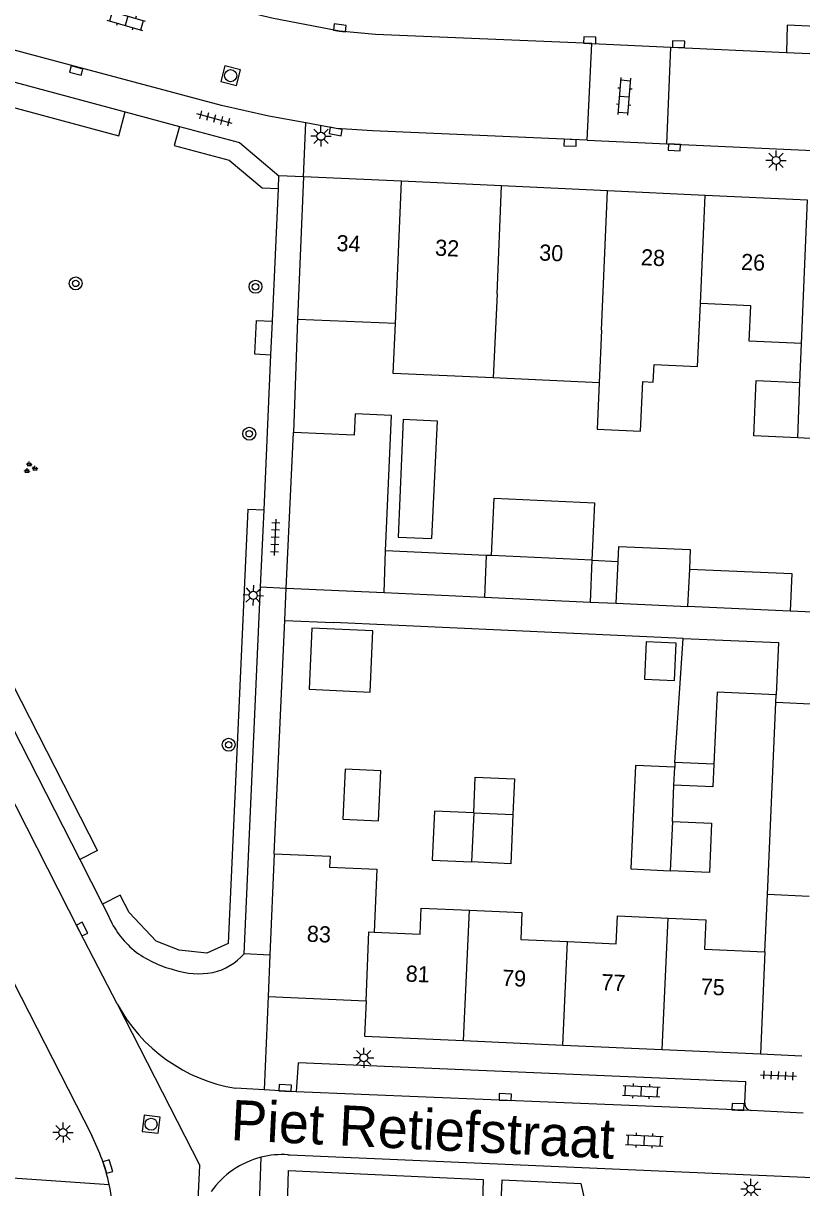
# Model space of a CAD drawing. Extents: x 132994 to 136000, y 393499 to 395512.
# Drawn here: x 133154 to 133202.2, y 395339 to 395411.1 of the extents above; entities that cross this region are included whole.
import ezdxf

# ---------------------------------------------------------------- set-up
doc = ezdxf.new("R2010")
doc.units = 0
for name, color, linetype in [('gg-afsc-erfafscheiding', 7, 'Continuous'), ('gg-afsc-hekwerk', 7, 'Continuous'), ('gg-afsc-muur', 7, 'Continuous'), ('gg-anno-huisnummerreeks BGT', 7, 'Continuous'), ('gg-anno-openbare ruimte label', 7, 'Continuous'), ('gg-bbg-bijgebouw', 7, 'Continuous'), ('gg-bbg-gedigitaliseerde bebouwing', 7, 'Continuous'), ('gg-bbg-gedigitaliseerde bijgebouw', 7, 'Continuous'), ('gg-bbg-hoofdgebouw', 7, 'Continuous'), ('gg-bbg-luifel en loopbrug', 7, 'Continuous'), ('gg-bbg-tussenscheiding', 7, 'Continuous'), ('gg-knt-verharding', 7, 'Continuous'), ('gg-knt-verharding nz', 7, 'Continuous'), ('gt-grn-groengrens', 7, 'Continuous'), ('gt-grn-weggrens', 7, 'Continuous'), ('gt-symb-boom', 7, 'Continuous'), ('gt-symb-groenvak', 7, 'Continuous'), ('gt-symb-klinker verharding', 7, 'Continuous'), ('gt-symb-kolk', 7, 'Continuous'), ('gt-symb-lichtmast', 7, 'Continuous'), ('gt-symb-rioolschacht', 7, 'Continuous'), ('gt-symb-tegel verharding', 7, 'Continuous')]:
    doc.layers.add(name, color=color, linetype=linetype)

# ---------------------------------------------------------------- blocks, each defined once
blk = doc.blocks.new('gt0-KOLK')
at = {"layer": 'gt-symb-kolk'}
blk.add_lwpolyline([(0, 0), (0.375, 0), (0.375, 0.4), (-0.375, 0.4), (-0.375, 0), (0, 0)], dxfattribs=at)
blk = doc.blocks.new('gt0-KL1')
at = {"layer": 'gt-symb-klinker verharding'}
for p, q in [((-1.15, 0.3), (1.15, 0.3)), ((-1, -0.3), (-1, 0.3)), ((-0.5, 0.3), (-0.5, 0.45)), ((0, -0.3), (0, 0.3)), ((0.5, 0.3), (0.5, 0.45)), ((1, -0.3), (1, 0.3)), ((-1.15, -0.3), (1.15, -0.3)), ((-0.5, -0.45), (-0.5, -0.3)), ((0.5, -0.45), (0.5, -0.3))]:
    blk.add_line(p, q, dxfattribs=at)
blk = doc.blocks.new('gt0-LMAST')
at = {"layer": 'gt-symb-lichtmast'}
for p, q in [((-0.182, 0.173), (-0.447, 0.438)), ((-0.005, 0.246), (-0.005, 0.621)), ((0.172, 0.173), (0.437, 0.438)), ((-0.255, -0.004), (-0.63, -0.004)), ((-0.182, -0.181), (-0.447, -0.446)), ((-0.005, -0.254), (-0.005, -0.629)), ((0.437, -0.446), (0.172, -0.181)), ((0.245, -0.004), (0.62, -0.004))]:
    blk.add_line(p, q, dxfattribs=at)
blk.add_circle((-0.005, -0.004), 0.25, dxfattribs=at)
blk = doc.blocks.new('gt0-TEG1')
at = {"layer": 'gt-symb-tegel verharding'}
for p, q in [((-1.125, 0), (1.125, 0)), ((-0.9, -0.25), (-0.9, 0.25)), ((-0.45, -0.25), (-0.45, 0.25)), ((0, -0.25), (0, 0.25)), ((0.45, -0.25), (0.45, 0.25)), ((0.9, -0.25), (0.9, 0.25))]:
    blk.add_line(p, q, dxfattribs=at)
blk = doc.blocks.new('gt0-BOOM')
at = {"layer": 'gt-symb-boom'}
for radius in [0.4, 0.2]:
    blk.add_circle((0, 0), radius, dxfattribs=at)
blk = doc.blocks.new('gt0-RS')
at = {"layer": 'gt-symb-rioolschacht'}
blk.add_lwpolyline([(-0.5, -0.5), (0.5, -0.5), (0.5, 0.5), (-0.5, 0.5)], close=True, dxfattribs=at)
blk.add_circle((0, 0), 0.375, dxfattribs=at)
blk = doc.blocks.new('gt0-GRVAK')
at = {"layer": 'gt-symb-groenvak'}
for p, q in [((-0.11, 0.189), (-0.228, 0.24)), ((-0.182, 0.153), (0.088, 0.153)), ((-0.091, 0.211), (-0.156, 0.322)), ((-0.047, 0.214), (-0.047, 0.393)), ((-0.004, 0.211), (0.061, 0.322)), ((0.015, 0.189), (0.133, 0.24)), ((0.262, -0.052), (0.197, 0.059)), ((0.305, -0.049), (0.305, 0.13)), ((0.349, -0.052), (0.414, 0.059)), ((-0.245, -0.228), (-0.363, -0.177)), ((-0.318, -0.264), (-0.047, -0.264)), ((-0.226, -0.206), (-0.291, -0.095)), ((-0.183, -0.203), (-0.183, -0.024)), ((-0.139, -0.206), (-0.074, -0.095)), ((-0.12, -0.228), (-0.002, -0.177)), ((0.243, -0.074), (0.125, -0.023)), ((0.17, -0.11), (0.441, -0.11)), ((0.368, -0.074), (0.486, -0.023))]:
    blk.add_line(p, q, dxfattribs=at)

msp = doc.modelspace()

# ---------------------------------------------------------------- linework, layer by layer
at = {"layer": 'gg-afsc-erfafscheiding'}
for p, q in [((133232.713, 395373.343), (133201.504, 395374.716)), ((133194.88, 395373.028), (133173.207, 395374.007)), ((133200.627, 395369.052), (133200.648, 395369.533)), ((133199.948, 395353.623), (133200.104, 395357.169))]:
    msp.add_line(p, q, dxfattribs=at)
at = {"layer": 'gg-afsc-hekwerk'}
for p, q in [((133170.21, 395374.142), (133170.3, 395376.14)), ((133199.67, 395347.31), (133202.23, 395347.18))]:
    msp.add_line(p, q, dxfattribs=at)
at = {"layer": 'gg-afsc-muur'}
for p, q in [((133170.99, 395392.77), (133170.74, 395385.78)), ((133169.555, 395359.692), (133170.21, 395374.142)), ((133170.21, 395374.142), (133173.207, 395374.007))]:
    msp.add_line(p, q, dxfattribs=at)
at = {"layer": 'gg-bbg-bijgebouw'}
msp.add_line((133170.3, 395376.14), (133170.74, 395385.78), dxfattribs=at)
msp.add_lwpolyline([(133173.809, 395361.838), (133176.009, 395361.722), (133176.161, 395364.82), (133173.955, 395364.928), (133173.809, 395361.838)], dxfattribs=at)
at = {"layer": 'gg-bbg-gedigitaliseerde bebouwing'}
for p, q in [((133177.065, 395392.515), (133170.99, 395392.77)), ((133202.11, 395388.875), (133202.222, 395391.286)), ((133189.68, 395388.845), (133183.119, 395389.149)), ((133175.908, 395358.733), (133175.748, 395354.841)), ((133199.948, 395353.623), (133199.67, 395347.31))]:
    msp.add_line(p, q, dxfattribs=at)
for points in [[(133189.68, 395388.845), (133189.547, 395385.989), (133192.246, 395385.864), (133192.387, 395388.927), (133193.031, 395388.897), (133193.082, 395389.993), (133195.779, 395389.868), (133195.96, 395393.768)], [(133202.222, 395391.286), (133198.972, 395391.436), (133199.073, 395393.624), (133195.96, 395393.768)], [(133183.119, 395389.149), (133176.922, 395389.436), (133177.065, 395392.515)], [(133205.425, 395391.093), (133205.315, 395388.726), (133204.925, 395388.745), (133204.766, 395385.305), (133201.976, 395385.434)], [(133175.748, 395354.841), (133178.591, 395354.716), (133178.662, 395356.331), (133181.645, 395356.2)], [(133181.645, 395356.2), (133184.895, 395356.057), (133184.821, 395354.382), (133187.723, 395354.254)], [(133187.723, 395354.254), (133190.738, 395354.121), (133190.814, 395355.838), (133193.951, 395355.699)], [(133193.951, 395355.699), (133196.29, 395355.596), (133196.21, 395353.788), (133199.948, 395353.623)]]:
    msp.add_lwpolyline(points, dxfattribs=at)
at = {"layer": 'gg-bbg-gedigitaliseerde bijgebouw'}
for p, q in [((133176.44, 395378.455), (133176.826, 395386.822)), ((133182.682, 395378.167), (133176.44, 395378.455)), ((133183.017, 395378.152), (133182.682, 395378.167)), ((133189.233, 395377.866), (133183.017, 395378.152)), ((133189.233, 395377.866), (133189.124, 395375.273)), ((133190.736, 395375.199), (133190.855, 395377.791)), ((133170.3, 395376.14), (133176.367, 395375.86)), ((133176.367, 395375.86), (133182.574, 395375.574)), ((133182.574, 395375.574), (133189.124, 395375.273)), ((133190.736, 395375.199), (133195.162, 395374.995)), ((133201.504, 395374.716), (133195.162, 395374.995)), ((133194.375, 395365.343), (133194.88, 395373.028)), ((133194.313, 395363.938), (133194.362, 395365.043)), ((133196.791, 395365.237), (133194.375, 395365.343)), ((133194.214, 395361.684), (133194.313, 395363.938)), ((133181.91, 395362.225), (133184.336, 395362.118))]:
    msp.add_line(p, q, dxfattribs=at)
for points in [[(133201.976, 395385.434), (133199.253, 395385.56), (133199.413, 395389.001), (133202.11, 395388.875)], [(133176.826, 395386.822), (133174.564, 395386.925), (133174.504, 395385.614), (133170.74, 395385.78)], [(133177.543, 395386.589), (133177.237, 395379.295), (133179.301, 395379.209)], [(133177.543, 395386.589), (133179.637, 395386.492), (133179.301, 395379.209)], [(133190.855, 395377.791), (133190.898, 395378.724), (133195.324, 395378.52), (133195.269, 395377.315)], [(133195.269, 395377.315), (133201.606, 395377.036), (133201.504, 395374.716)], [(133171.892, 395373.653), (133171.721, 395369.873), (133175.501, 395369.702), (133175.672, 395373.483), (133171.892, 395373.653)], [(133192.49, 395370.499), (133194.355, 395370.415), (133194.46, 395372.736), (133192.595, 395372.82), (133192.49, 395370.499)], [(133194.88, 395373.028), (133200.79, 395372.769), (133200.648, 395369.533)], [(133200.648, 395369.533), (133196.987, 395369.694), (133196.791, 395365.237)], [(133194.362, 395365.043), (133191.936, 395365.15), (133191.639, 395358.748), (133194.08, 395358.641)], [(133181.91, 395362.225), (133179.484, 395362.331), (133179.335, 395359.289), (133181.776, 395359.182)], [(133184.336, 395362.118), (133184.218, 395359.075), (133181.776, 395359.182)], [(133194.214, 395361.684), (133196.64, 395361.577), (133196.522, 395358.534), (133194.08, 395358.641)]]:
    msp.add_lwpolyline(points, dxfattribs=at)
at = {"layer": 'gg-bbg-hoofdgebouw'}
for p, q in [((133171.36, 395401.61), (133170.99, 395392.77)), ((133177.434, 395401.328), (133171.36, 395401.61)), ((133183.64, 395401.04), (133177.434, 395401.328)), ((133190.192, 395400.736), (133183.64, 395401.04)), ((133196.24, 395400.456), (133190.192, 395400.736)), ((133202.594, 395400.161), (133196.24, 395400.456)), ((133169.555, 395359.692), (133169.282, 395353.422)), ((133169.282, 395353.422), (133169.17, 395350.85)), ((133169.17, 395350.85), (133175.24, 395350.59)), ((133181.285, 395348.119), (133187.437, 395347.849)), ((133187.437, 395347.849), (133193.589, 395347.578)), ((133193.589, 395347.578), (133199.67, 395347.31))]:
    msp.add_line(p, q, dxfattribs=at)
for points in [[(133169.555, 395359.692), (133173.011, 395359.55), (133172.983, 395358.853), (133175.908, 395358.733)], [(133175.24, 395350.59), (133175.14, 395348.39), (133181.285, 395348.119)]]:
    msp.add_lwpolyline(points, dxfattribs=at)
at = {"layer": 'gg-bbg-luifel en loopbrug'}
for p, q in [((133189.233, 395377.866), (133190.855, 395377.791)), ((133189.124, 395375.273), (133190.736, 395375.199)), ((133200.104, 395357.169), (133200.627, 395369.052)), ((133203.2, 395368.936), (133200.627, 395369.052)), ((133194.375, 395365.343), (133194.362, 395365.043)), ((133202.677, 395357.053), (133200.104, 395357.169))]:
    msp.add_line(p, q, dxfattribs=at)
for points in [[(133183.017, 395378.152), (133183.182, 395381.71), (133189.399, 395381.42), (133189.233, 395377.866)], [(133196.791, 395365.237), (133196.727, 395363.829), (133194.313, 395363.938)], [(133181.91, 395362.225), (133182.01, 395364.439), (133184.436, 395364.33), (133184.336, 395362.118)]]:
    msp.add_lwpolyline(points, dxfattribs=at)
at = {"layer": 'gg-bbg-tussenscheiding'}
for p, q in [((133177.065, 395392.515), (133177.434, 395401.328)), ((133183.36, 395394.353), (133183.64, 395401.04)), ((133189.831, 395392.119), (133190.192, 395400.736)), ((133195.96, 395393.768), (133196.24, 395400.456)), ((133202.222, 395391.286), (133202.594, 395400.161)), ((133183.36, 395394.353), (133183.119, 395389.149)), ((133189.831, 395392.119), (133189.68, 395388.845)), ((133201.976, 395385.434), (133202.11, 395388.875)), ((133176.367, 395375.86), (133176.44, 395378.455)), ((133182.682, 395378.167), (133182.574, 395375.574)), ((133195.269, 395377.315), (133195.162, 395374.995)), ((133181.91, 395362.225), (133181.776, 395359.182)), ((133194.214, 395361.684), (133194.08, 395358.641)), ((133181.285, 395348.119), (133181.645, 395356.2)), ((133193.589, 395347.578), (133193.951, 395355.699)), ((133187.437, 395347.849), (133187.723, 395354.254))]:
    msp.add_line(p, q, dxfattribs=at)
msp.add_lwpolyline([(133175.24, 395350.59), (133175.424, 395354.855), (133175.748, 395354.841)], dxfattribs=at)
at = {"layer": 'gg-knt-verharding'}
for p, q in [((133144.097, 395409.987), (133160.331, 395405.623)), ((133188.944, 395403.874), (133189.225, 395409.857)), ((133189.225, 395409.857), (133194.128, 395409.632)), ((133193.88, 395403.65), (133194.128, 395409.632)), ((133194.128, 395409.632), (133201.286, 395409.308)), ((133160.331, 395405.623), (133163.678, 395404.723)), ((133163.678, 395404.723), (133167.41, 395403.72)), ((133167.41, 395403.72), (133169.85, 395401.67)), ((133188.944, 395403.874), (133193.88, 395403.65)), ((133193.88, 395403.65), (133249.653, 395401.117)), ((133169.815, 395400.884), (133169.85, 395401.67)), ((133169.447, 395392.664), (133169.815, 395400.884)), ((133169.354, 395390.59), (133169.447, 395392.664)), ((133168.925, 395380.989), (133169.354, 395390.59)), ((133168.711, 395376.209), (133168.925, 395380.989)), ((133167.695, 395353.491), (133168.711, 395376.209)), ((133149.375, 395359.614), (133158.252, 395342.244)), ((133157.505, 395359.337), (133158.919, 395356.566)), ((133158.919, 395356.566), (133159.291, 395355.838)), ((133171.033, 395346.742), (133170.915, 395344.947)), ((133168.922, 395345.067), (133167.152, 395345.174)), ((133170.915, 395344.947), (133168.922, 395345.067)), ((133202.308, 395343.639), (133199.097, 395343.792)), ((133170.4, 395341.059), (133170.527, 395341.054)), ((133170.527, 395341.054), (133214.626, 395339.147))]:
    msp.add_line(p, q, dxfattribs=at)
for points in [[(133171.51, 395404.943), (133169.223, 395405.351), (133166.292, 395406.012), (133144.543, 395411.814), (133143.654, 395411.997), (133142.75, 395412.072), (133141.604, 395412.044), (133140.475, 395411.844), (133139.66, 395411.594), (133138.873, 395411.247)], [(133189.225, 395409.857), (133175.83, 395410.426), (133173.589, 395410.632), (133169.415, 395411.418), (133166.603, 395412.113)], [(133225.744, 395408.191), (133225.778, 395409.871), (133201.323, 395410.99), (133201.286, 395409.308)], [(133188.944, 395403.874), (133175.633, 395404.456), (133173.395, 395404.606), (133171.51, 395404.943)], [(133136.235, 395401.257), (133136.578, 395400.328), (133157.505, 395359.337)], [(133159.835, 395350.392), (133157.474, 395354.933), (133147.067, 395375.376)], [(133198.704, 395344.269), (133198.772, 395345.561), (133171.033, 395346.742)], [(133170.448, 395340.07), (133182.495, 395339.529), (133182.411, 395336.662), (133170.364, 395337.203), (133170.448, 395340.07)], [(133183.545, 395336.623), (133183.674, 395339.499), (133188.551, 395339.265), (133188.892, 395337.732), (133188.807, 395336.801), (133188.715, 395336.38), (133183.545, 395336.623)]]:
    msp.add_lwpolyline(points, dxfattribs=at)
for centre, radius, start, end in [((133164.415, 395357.994), 5.559, 202.81386, 230.41615), ((133164.964, 395359.012), 6.698, 232.3516, 256.04634), ((133164.894, 395355.991), 3.755, 283.23202, 318.25191), ((133164.898, 395357.165), 4.904, 251.58608, 280.03946), ((133168.825, 395355.258), 10.222, 208.42894, 260.58316), ((133199.134, 395344.223), 0.432, 173.84601, 265.12417), ((133147.242, 395336.608), 12.368, 12.12042, 27.10838), ((133170.091, 395335.612), 5.457, 104.29317, 144.59988), ((133170.087, 395335.612), 5.456, 86.71473, 104.2541), ((133147.263, 395336.608), 12.349, 2.07799, 12.13923)]:
    msp.add_arc(centre, radius, start, end, dxfattribs=at)
at = {"layer": 'gg-knt-verharding nz'}
msp.add_line((133199.097, 395343.792), (133170.915, 395344.947), dxfattribs=at)
msp.add_lwpolyline([(133201.286, 395409.308), (133223.564, 395408.345), (133225.744, 395408.191)], dxfattribs=at)
at = {"layer": 'gt-grn-groengrens'}
for p, q in [((133168.801, 395400.929), (133169.815, 395400.884)), ((133168.433, 395392.709), (133168.341, 395390.635)), ((133168.433, 395392.709), (133169.447, 395392.664)), ((133168.341, 395390.635), (133169.354, 395390.59)), ((133167.911, 395381.035), (133168.925, 395380.989)), ((133158.604, 395359.898), (133157.505, 395359.337)), ((133160.018, 395357.127), (133158.919, 395356.566))]:
    msp.add_line(p, q, dxfattribs=at)
for points in [[(133158.604, 395359.898), (133137.681, 395400.882), (133137.452, 395402.456), (133137.596, 395403.831), (133138.055, 395405.279), (133138.802, 395406.557), (133140.201, 395407.957), (133141.6, 395408.632), (133142.951, 395408.608), (133144.277, 395408.343), (133159.931, 395404.135), (133160.331, 395405.623)], [(133163.678, 395404.723), (133163.363, 395403.553), (133166.768, 395402.637), (133168.801, 395400.929)], [(133167.911, 395381.035), (133166.708, 395354.133), (133165.382, 395353.526), (133163.669, 395353.719), (133162.246, 395354.274), (133160.564, 395356.058), (133160.018, 395357.127)]]:
    msp.add_lwpolyline(points, dxfattribs=at)
at = {"layer": 'gt-grn-weggrens'}
for p, q in [((133171.36, 395401.61), (133171.51, 395404.943)), ((133171.36, 395401.61), (133169.85, 395401.67)), ((133168.711, 395376.209), (133170.3, 395376.14)), ((133169.282, 395353.422), (133167.695, 395353.491)), ((133159.835, 395350.392), (133164.945, 395340.391)), ((133169.17, 395350.85), (133168.922, 395345.067)), ((133168.59, 395336.61), (133168.744, 395340.9)), ((133164.767, 395336.8), (133164.945, 395340.391)), ((133152.42, 395339.68), (133159.335, 395339.205))]:
    msp.add_line(p, q, dxfattribs=at)

# ---------------------------------------------------------------- block references
at = {"layer": 'gt-symb-boom'}
for p in [(133157.26, 395395.005), (133168.396, 395394.796), (133168.01, 395385.697), (133166.733, 395366.439)]:
    msp.add_blockref('gt0-BOOM', p, dxfattribs=at)
at = {"layer": 'gt-symb-groenvak'}
msp.add_blockref('gt0-GRVAK', (133154.433, 395383.579), dxfattribs=at)
at = {"layer": 'gt-symb-klinker verharding'}
for p, rotation in [((133160.4, 395411.258), 163.97589034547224), ((133191.234, 395406.583), -94.70180831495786), ((133192.295, 395344.992), -2.6936110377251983), ((133192.482, 395341.939), -2.5219079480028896)]:
    msp.add_blockref('gt0-KL1', p, dxfattribs=dict(at, rotation=rotation))
at = {"layer": 'gt-symb-kolk'}
for p, rotation in [((133173.589, 395410.632), -8.340866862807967), ((133189.091, 395409.861), -2.464663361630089), ((133194.589, 395409.615), -2.1210963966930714), ((133157.348, 395408.376), 164.99108632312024), ((133173.395, 395404.606), 169.85920685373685), ((133187.891, 395403.909), 177.42085249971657), ((133194.343, 395403.627), 177.13473427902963), ((133157.474, 395354.933), -62.983810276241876), ((133170.221, 395344.99), -2.7508347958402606), ((133183.852, 395344.424), -2.4074138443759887), ((133198.272, 395343.817), -1.7183580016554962), ((133159.059, 395340.263), -72.77930062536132)]:
    msp.add_blockref('gt0-KOLK', p, dxfattribs=dict(at, rotation=rotation))
at = {"layer": 'gt-symb-lichtmast'}
for p in [(133172.455, 395404.118), (133200.643, 395402.621), (133175.103, 395347.063), (133156.479, 395342.433), (133199.084, 395338.934)]:
    msp.add_blockref('gt0-LMAST', p, dxfattribs=at)
at = {"layer": 'gt-symb-lichtmast', "rotation": -92.46466335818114}
msp.add_blockref('gt0-LMAST', (133168.261, 395375.684), dxfattribs=at)
at = {"layer": 'gt-symb-rioolschacht'}
for p, rotation in [((133166.856, 395407.867), 165.5744682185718), ((133161.928, 395342.942), -96.71987988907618)]:
    msp.add_blockref('gt0-RS', p, dxfattribs=dict(at, rotation=rotation))
at = {"layer": 'gt-symb-tegel verharding'}
for p, rotation in [((133165.857, 395405.207), 164.93576605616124), ((133169.619, 395379.278), 87.36361809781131), ((133200.788, 395345.958), -2.4074138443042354)]:
    msp.add_blockref('gt0-TEG1', p, dxfattribs=dict(at, rotation=rotation))

# ---------------------------------------------------------------- texts
at = {"layer": 'gg-anno-huisnummerreeks BGT'}
for s, rotation, p in [('34', 357.4, (133173.393, 395397.01)), ('32', 357.4, (133179.501, 395396.727)), ('30', 357.4, (133185.949, 395396.427)), ('28', 357.4, (133192.25, 395396.135)), ('26', 357.4, (133198.45, 395395.848)), ('83', 357.5, (133171.56, 395354.251)), ('81', 357.5, (133177.682, 395351.781)), ('79', 357.5, (133183.648, 395351.518)), ('77', 357.5, (133189.796, 395351.248)), ('75', 357.5, (133195.953, 395350.977))]:
    msp.add_text(s, height=1, rotation=rotation, dxfattribs=at).set_placement(p)
at = {"layer": 'gg-anno-openbare ruimte label'}
msp.add_text('Piet Retiefstraat', height=2.5, rotation=357.2, dxfattribs=at).set_placement((133166.83, 395341.962))

doc.saveas('drawing.dxf')
